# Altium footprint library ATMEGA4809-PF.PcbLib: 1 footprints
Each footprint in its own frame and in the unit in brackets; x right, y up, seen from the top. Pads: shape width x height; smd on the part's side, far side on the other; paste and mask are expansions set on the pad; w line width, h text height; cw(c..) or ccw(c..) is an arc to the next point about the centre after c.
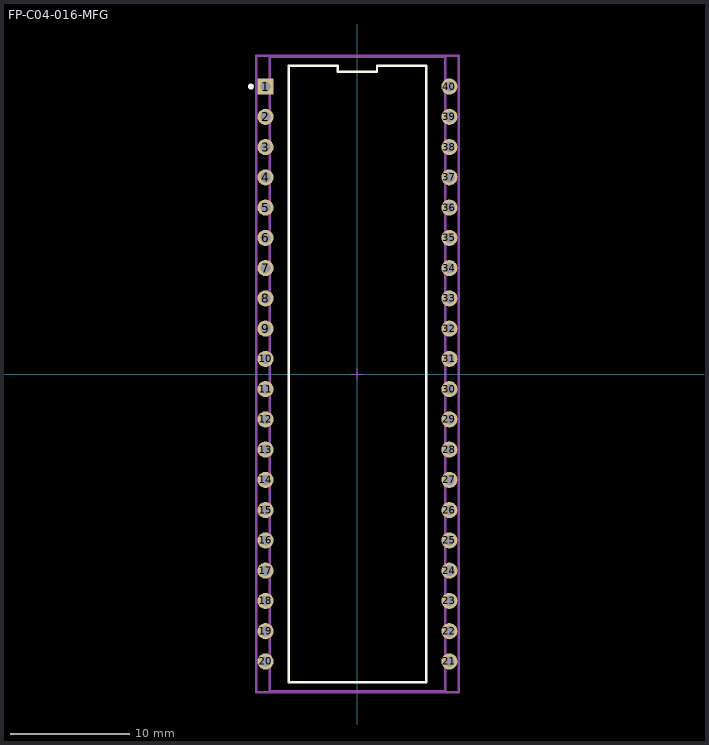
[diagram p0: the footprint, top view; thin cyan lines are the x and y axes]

## FP-C04-016-MFG [mm]
pads (40):
  rect 1.35x1.35 hole 0.85 paste-2539.97 mask+0: 1(-7.715,24.13)
  round 1.35 hole 0.85 paste-2539.97 mask+0: 2(-7.715,21.59) 3(-7.715,19.05) 4(-7.715,16.51) 5(-7.715,13.97) 6(-7.715,11.43) 7(-7.715,8.89) 8(-7.715,6.35) 9(-7.715,3.81) 10(-7.715,1.27) 11(-7.715,-1.27) 12(-7.715,-3.81) 13(-7.715,-6.35) 14(-7.715,-8.89) 15(-7.715,-11.43) 16(-7.715,-13.97) 17(-7.715,-16.51) 18(-7.715,-19.05) 19(-7.715,-21.59) 20(-7.715,-24.13) 21(7.715,-24.13) 22(7.715,-21.59) 23(7.715,-19.05) 24(7.715,-16.51) 25(7.715,-13.97) 26(7.715,-11.43) 27(7.715,-8.89) 28(7.715,-6.35) 29(7.715,-3.81) 30(7.715,-1.27) 31(7.715,1.27) 32(7.715,3.81) 33(7.715,6.35) 34(7.715,8.89) 35(7.715,11.43) 36(7.715,13.97) 37(7.715,16.51) 38(7.715,19.05) 39(7.715,21.59) 40(7.715,24.13)
Top Overlay:
  circle w0.25: c-8.94,24.13 r0.125
  lines w0.2: -5.763,-25.876 5.763,-25.876 5.763,25.876 1.646,25.876 1.646,25.376 -1.646,25.376 -1.646,25.876 -5.763,25.876 -5.763,-25.876
Top Assembly:
  lines w0.2: -8.49,-26.706 -8.49,26.706 8.49,26.706 8.49,-26.706 -8.49,-26.706
  text ".Designator" at 0,0.188 h1
Top 3D Body:
  lines w0.2: -7.366,-26.607 -7.366,26.607 7.366,26.607 7.366,-26.607 -7.366,-26.607
Top Courtyard:
  lines w0.2: -8.49,-26.706 -8.49,26.706 8.49,26.706 8.49,-26.706 -8.49,-26.706
Top Component Center:
  lines w0.1: -0.5,0 0.5,0 ; 0,-0.5 0,0.5
3D body "IC_Microchip_Technology_PIC18LF47K40-I-P_eec.STEP": height 0.25, standoff 0, extent -8.49,-26.706 8.49,26.706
